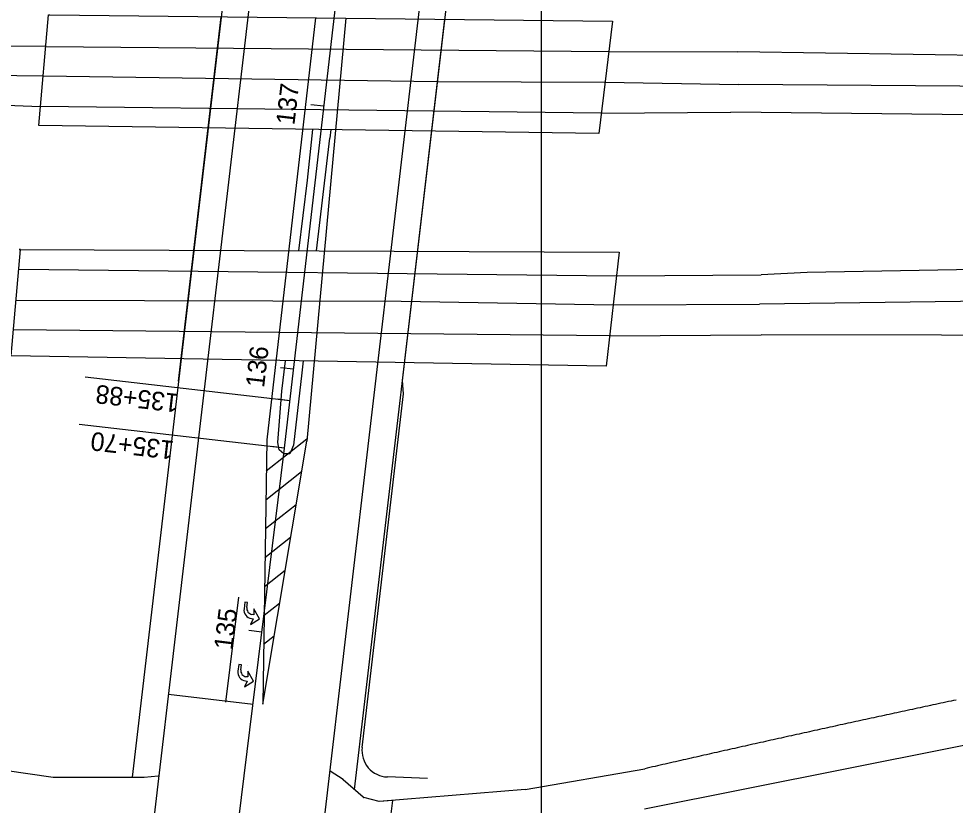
# Model space of a CAD drawing. Extents: x 2318076 to 2324211, y 613525 to 630327.
# Drawn here: x 2320472.4 to 2320826.1, y 628005.7 to 628302.7 of the extents above; entities that cross this region are included whole.
import ezdxf

# ---------------------------------------------------------------- set-up
doc = ezdxf.new("R2010")
doc.units = 0
for name, color, linetype in [('BR_X_Slab_Object', 7, 'Continuous'), ('GE_P_CL_50', 7, 'Continuous'), ('GE_X_CL_50', 7, 'Continuous'), ('PM_P_Cells', 7, 'Continuous'), ('PM_P_Channelizing_Line', 7, 'Continuous'), ('PM_P_CL_Double_Solid', 7, 'Continuous'), ('PM_P_Stop_Line', 7, 'Continuous'), ('PM_P_Transverse_Line', 7, 'Continuous'), ('PV_P_EOP', 7, 'Continuous'), ('PV_P_Shoulder', 7, 'Continuous'), ('RD_X_Concrete_Barrier', 7, 'Continuous'), ('RD_X_GR_Rt', 7, 'Continuous'), ('RS_Raster1', 7, 'Continuous'), ('SC_Scratch3', 7, 'Continuous'), ('TX_P_1', 7, 'Continuous')]:
    doc.layers.add(name, color=color, linetype=linetype)

msp = doc.modelspace()

# ---------------------------------------------------------------- linework, layer by layer
at = {"layer": 'BR_X_Slab_Object'}
for points in [[(2320484.11, 628304.16), (2320696.64, 628301.84), (2320691.49, 628259.41), (2320480.05, 628262.45), (2320483.63, 628304.22), (2320484.11, 628304.16)], [(2320472.62, 628215.62), (2320699.2, 628214.57), (2320694.19, 628171.55), (2320469.54, 628175.38), (2320473.07, 628215.6), (2320472.62, 628215.62)]]:
    msp.add_lwpolyline(points, dxfattribs=at)
at = {"layer": 'GE_P_CL_50'}
for p, q in [((2320587.68, 628269.7), (2320582.71, 628270.28)), ((2320576.2, 628170.36), (2320571.24, 628170.94)), ((2320574.82, 628158.44), (2320497.49, 628167.38)), ((2320574.97, 628158.43), (2320570.01, 628159.03)), ((2320572.76, 628140.56), (2320495.27, 628149.51)), ((2320572.77, 628140.56), (2320567.81, 628141.17)), ((2320564.24, 628071.08), (2320559.28, 628071.69))]:
    msp.add_line(p, q, dxfattribs=at)
msp.add_lwpolyline([(2320476.3, 627307.7), (2320485.22, 627375.57), (2320502.11, 627520.92), (2320519.22, 627676.47), (2320531.82, 627783.89), (2320546.8, 627927.12), (2320554.45, 627991.34), (2320572.51, 628138.41), (2320649.52, 628804.84), (2320678.77, 629064.5), (2320690.76, 629163.78), (2320713.75, 629362.45), (2320725.26, 629461.78), (2320736.97, 629561.09), (2320748.4, 629660.43), (2320759.09, 629759.86), (2320769.62, 629859.3), (2320777.51, 629931.12), (2320778.25, 629937.84)], dxfattribs=at)
at = {"layer": 'GE_X_CL_50'}
for p, q in [((2320693.84, 628278.81), (2320744.17, 628277.94)), ((2320696.89, 628194.75), (2320752.2, 628194.93))]:
    msp.add_line(p, q, dxfattribs=at)
for points in [[(2318838.45, 628297.22), (2318989.13, 628295.38), (2319088.09, 628295.11), (2319168.95, 628294.58), (2319288.86, 628293.23), (2319411.65, 628291.27), (2319534.7, 628290.63), (2319653.02, 628288.28), (2319787.77, 628287.82), (2319899.47, 628286.31), (2320023.98, 628283.93), (2320152.65, 628284.01), (2320313.42, 628283.33), (2320481.66, 628281.19)], [(2320481.66, 628281.19), (2320630.42, 628279.04), (2320693.84, 628278.81)], [(2324211.2, 628237.88), (2324100.06, 628239.11), (2323887.64, 628240.84), (2323663.24, 628242.75), (2323428.01, 628246.39), (2323213.46, 628248.27), (2322983.92, 628250.37), (2322767.24, 628252.05), (2322547.46, 628255.46), (2322330.87, 628255.46), (2322180.02, 628258.17), (2321966.82, 628260.25), (2321752.93, 628261.56), (2321536.81, 628262.78), (2321340.76, 628266.62), (2321134.19, 628270.5), (2320911.42, 628276.64), (2320744.17, 628277.94)], [(2324209.54, 628169.05), (2324083.71, 628171.5), (2323932.07, 628172.99), (2323766.88, 628174.57), (2323590.27, 628175.99), (2323408.74, 628177.82), (2323205.61, 628179.86), (2322996.88, 628181.76), (2322795.55, 628183.99), (2322599.35, 628185.59), (2322419.03, 628185.84), (2322219.16, 628188.61), (2322096.17, 628189.9), (2321916.88, 628191.94), (2321753.71, 628193.94), (2321590.88, 628195.93), (2321431.73, 628197.42), (2321257.02, 628198.59), (2321067.83, 628197.06), (2320865.89, 628196.4), (2320752.2, 628194.93)], [(2320471.39, 628196.41), (2320616.88, 628196.07), (2320696.89, 628194.75)]]:
    msp.add_lwpolyline(points, dxfattribs=at)
at = {"layer": 'PM_P_Cells'}
for p, q in [((2320557.86, 628082.39), (2320557.49, 628079.94)), ((2320558.85, 628082.25), (2320557.86, 628082.39)), ((2320558.57, 628080.4), (2320558.85, 628082.25)), ((2320561.15, 628081.9), (2320561.15, 628081.9)), ((2320561.2, 628077.69), (2320560.51, 628077.79)), ((2320563.32, 628076.08), (2320561.2, 628079.96)), ((2320561.2, 628079.96), (2320561.2, 628077.69)), ((2320560.97, 628076.11), (2320559.98, 628073.99)), ((2320559.98, 628073.99), (2320563.32, 628076.08)), ((2320559.98, 628073.99), (2320559.98, 628073.99)), ((2320560.31, 628076.21), (2320560.97, 628076.11)), ((2320555.58, 628058.86), (2320555.21, 628056.41)), ((2320556.57, 628058.71), (2320555.58, 628058.86)), ((2320556.29, 628056.87), (2320556.57, 628058.71)), ((2320558.88, 628058.37), (2320558.88, 628058.37)), ((2320561.04, 628052.55), (2320558.92, 628056.42)), ((2320558.92, 628056.42), (2320558.92, 628054.16)), ((2320558.69, 628052.57), (2320557.7, 628050.45)), ((2320557.7, 628050.45), (2320561.04, 628052.55)), ((2320558.03, 628052.67), (2320558.69, 628052.57)), ((2320558.92, 628054.16), (2320558.23, 628054.26)), ((2320557.7, 628050.45), (2320557.7, 628050.45))]:
    msp.add_line(p, q, dxfattribs=at)
for centre, radius, end in [((2320560.74, 628079.46), 3.28, 262.4632), ((2320560.84, 628080.07), 2.3, 261.5547), ((2320558.46, 628055.92), 3.28, 262.4632), ((2320558.57, 628056.53), 2.3, 261.5547)]:
    msp.add_arc(centre, radius, 171.5547, end, dxfattribs=at)
at = {"layer": 'PM_P_Channelizing_Line'}
msp.add_lwpolyline([(2320550.68, 628044.66), (2320555.55, 628084.31)], dxfattribs=at)
at = {"layer": 'PM_P_CL_Double_Solid'}
for p, q in [((2320566.09, 628143.74), (2320564.56, 628043.85)), ((2320564.56, 628043.85), (2320581.17, 628143.24))]:
    msp.add_line(p, q, dxfattribs=at)
at = {"layer": 'PM_P_Stop_Line'}
msp.add_line((2320560.89, 628043.75), (2320528.92, 628047.49), dxfattribs=at)
at = {"layer": 'PM_P_Transverse_Line'}
for p, q in [((2320581.24, 628144), (2320565.91, 628131.86)), ((2320579.23, 628131.63), (2320565.74, 628120.95)), ((2320577.16, 628119.22), (2320565.58, 628110.05)), ((2320575.08, 628106.8), (2320565.41, 628099.14)), ((2320573.01, 628094.39), (2320565.24, 628088.24)), ((2320570.93, 628081.97), (2320565.07, 628077.33)), ((2320568.85, 628069.56), (2320564.9, 628066.43))]:
    msp.add_line(p, q, dxfattribs=at)
at = {"layer": 'PV_P_EOP'}
for p, q in [((2320590.74, 628574.92), (2320513.05, 627912.02)), ((2320576.7, 627905.37), (2320654.32, 628567.57)), ((2320584.51, 628303.06), (2320566.09, 628143.74)), ((2320595.94, 628302.94), (2320581.17, 628143.24)), ((2320594.89, 628015.41), (2320589.97, 628018.59)), ((2320602.43, 628008.79), (2320594.99, 628015.33)), ((2320608.54, 628007.18), (2320602.78, 628008.61)), ((2320613.63, 628007.58), (2320608.54, 628007.18))]:
    msp.add_line(p, q, dxfattribs=at)
msp.add_lwpolyline([(2320609.79, 627975.91), (2320611.27, 627988.34), (2320613.63, 628007.58)], dxfattribs=at)
for centre, start, end in [((2320594.44, 628014.71), 48.6772, 57.1121), ((2320602.98, 628009.42), 228.6772, 256.0413)]:
    msp.add_arc(centre, 0.833, start, end, dxfattribs=at)
at = {"layer": 'PV_P_Shoulder'}
for p, q in [((2320567.18, 628459.79), (2320515.22, 628016.39)), ((2320599.22, 628011.62), (2320651.77, 628459.98))]:
    msp.add_line(p, q, dxfattribs=at)
at = {"layer": 'RD_X_Concrete_Barrier'}
for p, q in [((2320532.74, 628165.9), (2320548.86, 628303.45)), ((2320617.32, 628166.06), (2320633.31, 628302.53)), ((2320590.26, 628260.87), (2320589.95, 628257.65)), ((2320589.78, 628257.63), (2320584.73, 628215.1))]:
    msp.add_line(p, q, dxfattribs=at)
for points in [[(2320578.2, 628215.13), (2320581.45, 628241.83), (2320583.5, 628260.96)], [(2320579.8, 628173.5), (2320579.27, 628169.07), (2320576.16, 628141.69), (2320574.82, 628138.47), (2320572.51, 628138.41), (2320570.8, 628139.9), (2320570.22, 628142.76), (2320571.74, 628162.06), (2320573.15, 628173.61)]]:
    msp.add_lwpolyline(points, dxfattribs=at)
at = {"layer": 'RD_X_GR_Rt'}
for p, q in [((2320617.74, 628161.06), (2320617.32, 628166.06)), ((2320602.09, 628027.57), (2320617.74, 628161.06)), ((2320626.8, 628015.81), (2320611.63, 628016.41))]:
    msp.add_line(p, q, dxfattribs=at)
msp.add_arc((2320612.03, 628026.4), 10, 173.3152, 267.7232, dxfattribs=at)
at = {"layer": 'RS_Raster1'}
for p, q in [((2320461.2, 628292.32), (2320482.62, 628292.44)), ((2320482.6, 628292.26), (2320695.24, 628290.34)), ((2320695.24, 628290.34), (2320743.98, 628290.21)), ((2320459.66, 628270.38), (2320480.66, 628269.62)), ((2320692.42, 628267.1), (2320480.67, 628269.63)), ((2320692.42, 628267.1), (2320741.34, 628267.39)), ((2320472.42, 628208.2), (2320698.17, 628205.7)), ((2320770.14, 628206.88), (2320752.78, 628205.99)), ((2320695.53, 628183.05), (2320470.4, 628185.22)), ((2320594.89, 628015.41), (2320590.03, 628018.55)), ((2320663.67, 628011.61), (2320708.82, 628019.53)), ((2320663.67, 628011.61), (2320608.54, 628007.18)), ((2320608.54, 628007.18), (2320602.78, 628008.61))]:
    msp.add_line(p, q, dxfattribs=at)
for points in [[(2321697.05, 628274.02), (2321509.24, 628275.49), (2321370.91, 628277.11), (2321223.2, 628279.67), (2321052.69, 628284.46), (2320876.34, 628288.23), (2320743.98, 628290.21)], [(2324210.96, 628226.01), (2324099.22, 628227.57), (2323922.84, 628229.43), (2323739.86, 628231.28), (2323551.5, 628233.43), (2323336.85, 628235.53), (2323118.39, 628237.8), (2322909.54, 628239.37), (2322678.89, 628242.27), (2322452.59, 628244.32), (2322252.25, 628245.65), (2322069.8, 628245.81), (2321869.81, 628248.03), (2321681.36, 628250.63), (2321451.01, 628251.29), (2321296.61, 628255.84), (2321123.18, 628260.35), (2320935.09, 628265.29), (2320741.34, 628267.39)], [(2324210.07, 628180.67), (2324126.99, 628181.82), (2323958.68, 628184.57), (2323765.72, 628185.78), (2323548.27, 628187.93), (2323298.91, 628189.99), (2323072.28, 628191.93), (2322817.32, 628194.08), (2322597.41, 628196.59), (2322367.08, 628198.37), (2322155.33, 628199.98), (2321962.28, 628202.76), (2321790.39, 628204.89), (2321604.43, 628210.03), (2321438.69, 628212.52), (2321272.37, 628212.78), (2321119.1, 628211.16), (2320939.43, 628209.93), (2320770.14, 628206.88)], [(2320698.17, 628205.7), (2320698.17, 628205.7), (2320752.83, 628205.99)], [(2319189.51, 628197.31), (2319278.1, 628191.01), (2319395.77, 628176.98), (2319442.58, 628171.23), (2319554.55, 628155.67), (2319664, 628139.56), (2319756.39, 628124.2), (2319834.01, 628113.24), (2319936.02, 628098.51), (2320027.26, 628084.66), (2320115.57, 628071.64), (2320199.48, 628059.37), (2320283.19, 628046.33), (2320384.46, 628030.93), (2320485.38, 628016.39)], [(2320695.53, 628183.05), (2320695.53, 628183.05), (2320752.78, 628183.39)], [(2321865.45, 628179.25), (2321679, 628181.71), (2321540.89, 628182.89), (2321384.45, 628185.57), (2321228.86, 628185.44), (2321052.77, 628183.94), (2320889, 628183.16), (2320752.78, 628183.39)], [(2321179.73, 628096.75), (2321032.45, 628067.95), (2320861.47, 628034.7), (2320708.68, 628004.26)], [(2320826.41, 628045.47), (2320825.44, 628045.27), (2320824.47, 628045.06), (2320823.49, 628044.85), (2320822.52, 628044.64), (2320821.55, 628044.44), (2320820.57, 628044.23), (2320819.6, 628044.02), (2320818.63, 628043.81), (2320817.65, 628043.6), (2320816.68, 628043.4), (2320815.71, 628043.19), (2320814.73, 628042.98), (2320813.76, 628042.77), (2320812.79, 628042.56), (2320811.81, 628042.35), (2320810.84, 628042.14), (2320809.87, 628041.93), (2320808.9, 628041.73), (2320807.92, 628041.52), (2320806.95, 628041.31), (2320805.98, 628041.1), (2320805, 628040.89), (2320804.03, 628040.68), (2320803.06, 628040.47), (2320802.09, 628040.26), (2320801.11, 628040.05), (2320800.14, 628039.84), (2320799.17, 628039.63), (2320798.19, 628039.42), (2320797.22, 628039.21), (2320796.25, 628038.99), (2320795.28, 628038.78), (2320794.3, 628038.57), (2320793.33, 628038.36), (2320792.36, 628038.15), (2320791.39, 628037.94), (2320790.41, 628037.73), (2320789.44, 628037.52), (2320788.47, 628037.3), (2320787.5, 628037.09), (2320786.52, 628036.88), (2320785.55, 628036.67), (2320784.58, 628036.46), (2320783.61, 628036.24), (2320782.63, 628036.03), (2320781.66, 628035.82), (2320780.69, 628035.61), (2320779.72, 628035.39), (2320778.75, 628035.18), (2320777.77, 628034.97), (2320776.8, 628034.75), (2320775.83, 628034.54), (2320774.86, 628034.33), (2320773.89, 628034.11), (2320772.91, 628033.9), (2320771.94, 628033.69), (2320770.97, 628033.47), (2320770, 628033.26), (2320769.03, 628033.04), (2320768.05, 628032.83), (2320767.08, 628032.61), (2320766.11, 628032.4), (2320765.14, 628032.19), (2320764.17, 628031.97), (2320763.19, 628031.76), (2320762.22, 628031.54), (2320761.25, 628031.33), (2320760.28, 628031.11), (2320759.31, 628030.89), (2320758.34, 628030.68), (2320757.36, 628030.46), (2320756.39, 628030.25), (2320755.42, 628030.03), (2320754.45, 628029.82), (2320753.48, 628029.6), (2320752.51, 628029.38), (2320751.54, 628029.17), (2320750.56, 628028.95), (2320749.59, 628028.73), (2320748.62, 628028.52), (2320747.65, 628028.3), (2320746.68, 628028.08), (2320745.71, 628027.87), (2320744.74, 628027.65), (2320743.77, 628027.43), (2320742.79, 628027.21), (2320741.82, 628027), (2320740.85, 628026.78), (2320739.88, 628026.56), (2320738.91, 628026.34), (2320737.94, 628026.13), (2320736.97, 628025.91), (2320736, 628025.69), (2320735.03, 628025.47), (2320734.05, 628025.25), (2320733.08, 628025.03), (2320732.11, 628024.82), (2320731.14, 628024.6), (2320730.17, 628024.38), (2320729.2, 628024.16), (2320728.23, 628023.94), (2320727.26, 628023.72), (2320726.29, 628023.5), (2320725.32, 628023.28), (2320724.35, 628023.06), (2320723.38, 628022.84), (2320722.41, 628022.62), (2320721.44, 628022.4), (2320720.46, 628022.18), (2320719.49, 628021.96), (2320718.52, 628021.74), (2320717.55, 628021.52), (2320716.58, 628021.3), (2320715.61, 628021.08), (2320714.64, 628020.86), (2320713.67, 628020.64), (2320712.7, 628020.42), (2320711.73, 628020.19), (2320710.76, 628019.97), (2320709.79, 628019.75), (2320708.82, 628019.53)], [(2320485.38, 628016.39), (2320494.26, 628016.39), (2320499.53, 628016.39), (2320508.04, 628016.39), (2320519.83, 628016.39), (2320525.1, 628016.85)], [(2320602.43, 628008.79), (2320598.76, 628012.02), (2320594.99, 628015.33)]]:
    msp.add_lwpolyline(points, dxfattribs=at)
for centre, start, end in [((2320594.44, 628014.71), 48.6772, 57.1121), ((2320602.98, 628009.42), 228.6772, 256.0413)]:
    msp.add_arc(centre, 0.833, start, end, dxfattribs=at)
at = {"layer": 'SC_Scratch3'}
msp.add_line((2320669.87, 614778.41), (2320669.87, 630327.22), dxfattribs=at)
at = {"layer": 'TX_P_1'}
for p, q in [((2320482.23, 628292.44), (2320482.62, 628292.44)), ((2320482.6, 628292.26), (2320482.32, 628292.44)), ((2320480.33, 628269.63), (2320480.67, 628269.63))]:
    msp.add_line(p, q, dxfattribs=at)

# ---------------------------------------------------------------- texts
at = {"layer": 'GE_P_CL_50'}
for s, rotation, p in [('137', 83.4084, (2320576.51, 628262.39)), ('136', 83.4084, (2320565.05, 628163.2)), ('135+88', 173.4084, (2320533.16, 628160.94)), ('135+70', 173.4084, (2320531.34, 628143.17)), ('135', 82.9992, (2320553.06, 628064.13))]:
    msp.add_text(s, height=7, rotation=rotation, dxfattribs=at).set_placement(p)

doc.saveas('drawing.dxf')
